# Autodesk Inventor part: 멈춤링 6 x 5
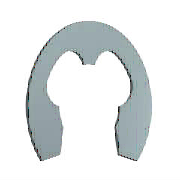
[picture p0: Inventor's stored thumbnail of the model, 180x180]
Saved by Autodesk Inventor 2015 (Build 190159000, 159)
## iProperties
Created: 2012-02
Part Number: 멈춤링 6 x 5
Material: 강철, 연강
Description: 스프링 리테이닝 링
Document SubType Name: Modeling
Standard: JIS B 2805
Designer: mduedu
Standards Organization: JIS
Language: ko-KR
Size Designation: 5
Categories: <MemberInstance><Categories><Category DisplayName="샤프트 부품" InternalName="7f7aeb1f-a693-4053-b835-cee3144e0d98" Mnemonic="SHFT"><Category DisplayName="써클립" Inter
Density: 1 g/cm^3
Appearance: 파란색 - 벽 페인트 - 광택
IsCustomPart: 1
Author: mduedu
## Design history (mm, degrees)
sketch "스케치1"
  geometry: L1 (-0.5, 0.024)-(0, 0.024) reference; L2 (-3.206, 0)-(3.486, 0) reference; L3 (-2.291, -3.976)-(2.291, -3.976); L4 (0, 1.949)-(0, -3.479) reference; L5 (-3, -1.976)-(-2.51, -1.976); L6 (-0.5, 0.024)-(-0.5, 0.509); L7 (0, 2.524)-(2.53, 2.524); L8 (-2.291, -3.976)-(-3.051, -6.131); L9 (0, -0.476)-(-1.278, -0.476); L10 (2.291, -3.976)-(3.051, -6.131); L11 (3, -1.976)-(2.51, -1.976); L12 (0.5, 0.024)-(0.5, 0.509); C1 r 3 at (0, -2.976); A1 r 2.5 centre (0, -2.976) between (-2.368, -2.174) and (-2.291, -3.976); A2 r 0.5 centre (0, 0.024) between (-0.5, 0.024) and (0.5, 0.024); A3 r 5.5 centre (0, -2.976) between (4.351, -6.34) and (-4.351, -6.34); A4 r 4 centre (0, -2.976) between (-1, 0.897) and (-3.529, -1.094); A5 r 0.4 centre (-0.9, 0.509) between (-0.5, 0.509) and (-1, 0.897); A6 r 0.6 centre (-3, -1.376) between (-3.529, -1.094) and (-3, -1.976); A7 r 0.15 centre (-2.51, -2.126) between (-2.368, -2.174) and (-2.51, -1.976); A8 r 0.75 centre (-3.758, -5.881) between (-4.351, -6.34) and (-3.051, -6.131); A9 r 0.75 centre (3.758, -5.881) between (3.051, -6.131) and (4.351, -6.34); A10 r 2.5 centre (0, -2.976) between (2.291, -3.976) and (2.368, -2.174); A11 r 0.15 centre (2.51, -2.126) between (2.51, -1.976) and (2.368, -2.174); A12 r 0.6 centre (3, -1.376) between (3, -1.976) and (3.529, -1.094); A13 r 4 centre (0, -2.976) between (3.529, -1.094) and (1, 0.897); A14 r 0.4 centre (0.9, 0.509) between (1, 0.897) and (0.5, 0.509); 1 further point
  constraints: 30 point on circle, 20 end point, 15 centre point, 13 symmetric about line, 12 tangent, 8 point on line, 4 parallel, 2 coincident, 2 horizontal, 1 concentric, 1 perpendicular, 1 vertical alignment, 9 other
  dimensions: "d0" = 6 diameter of C1 (= WD); "d3" = 1 distance from line of A1.centre L3 (= 0.2 x ND); "d4" = 0.5 radius of A2 (= 0.1 x ND); "d5" = 11 diameter of A3 (= SD2); "d8" = 4 radius of A4 (= 0.8 x ND); "d9" = 1 distance from line of A1.centre L5 (= 0.2 x ND); "d10" = 0.4 radius of A5 (= 0.08 x ND); "d11" = 0.6 radius of A6 (= 0.12 x ND); "d12" = 0.15 radius of A7 (= 0.03 x ND); "d13" = 0.75 radius of A8 (= 0.15 x ND); "d14" = 2.5 distance from line of A1.centre L9 (= 0.5 x ND); "d15" = 2.5 radius of A1 (= 0.5 x ND)
extrude "본체" new body sketch "스케치1" distance "d16" = 0.6 (= SD); taper "d17" = 0 deg
workaxis "Work Axis1"
workaxis "Work Axis2"
workplane "Work Plane1"
body "Solid1"
other parameters: "ND" = 5 [user parameter; used in 14 equation terms], "SD" = 0.6 [user parameter; used in 1 equation term], "WD" = 6 (= WDMIN) [user parameter; used in 1 equation term], "d1" = 8 (= 1.6 x ND), "d2" = 5 (= ND), "SD2" = 11 [user parameter; used in 1 equation term], "d6" = 5 (= ND), "d7" = 0.75 (= 0.15 x ND), "d18" = 0, "d19" = 0, "d27" = 0, "d28" = 0, "WDMIN" = 6 [user parameter; used in 1 equation term], "SNB" = 0.7 [user parameter], "WDMAX" = 8 [user parameter], "BUBRMI" = 1.2 [user parameter]
